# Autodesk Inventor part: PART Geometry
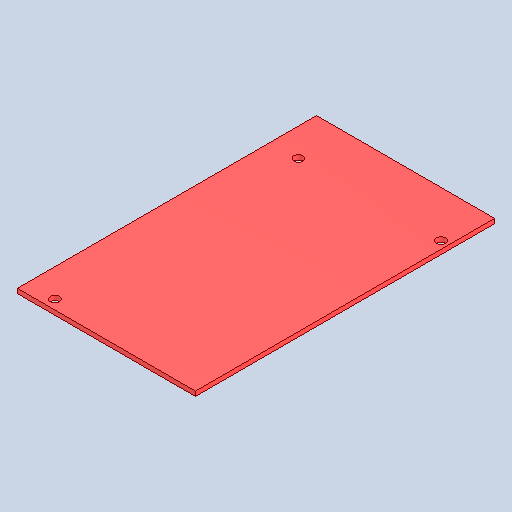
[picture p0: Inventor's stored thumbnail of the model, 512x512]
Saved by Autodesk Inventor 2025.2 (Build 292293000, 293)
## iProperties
Created: 2025-04
Part Number: PART Geometry
Material: Generic
Description: PART-PART Geometry-DESC
Document SubType Name: Modeling
Designer: BennF
Density: 1 g/cm^3
Appearance: Default
Author: BennF
Revision Number: NONE
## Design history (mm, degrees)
feature "Board-RipRap"
body "Solid1"
